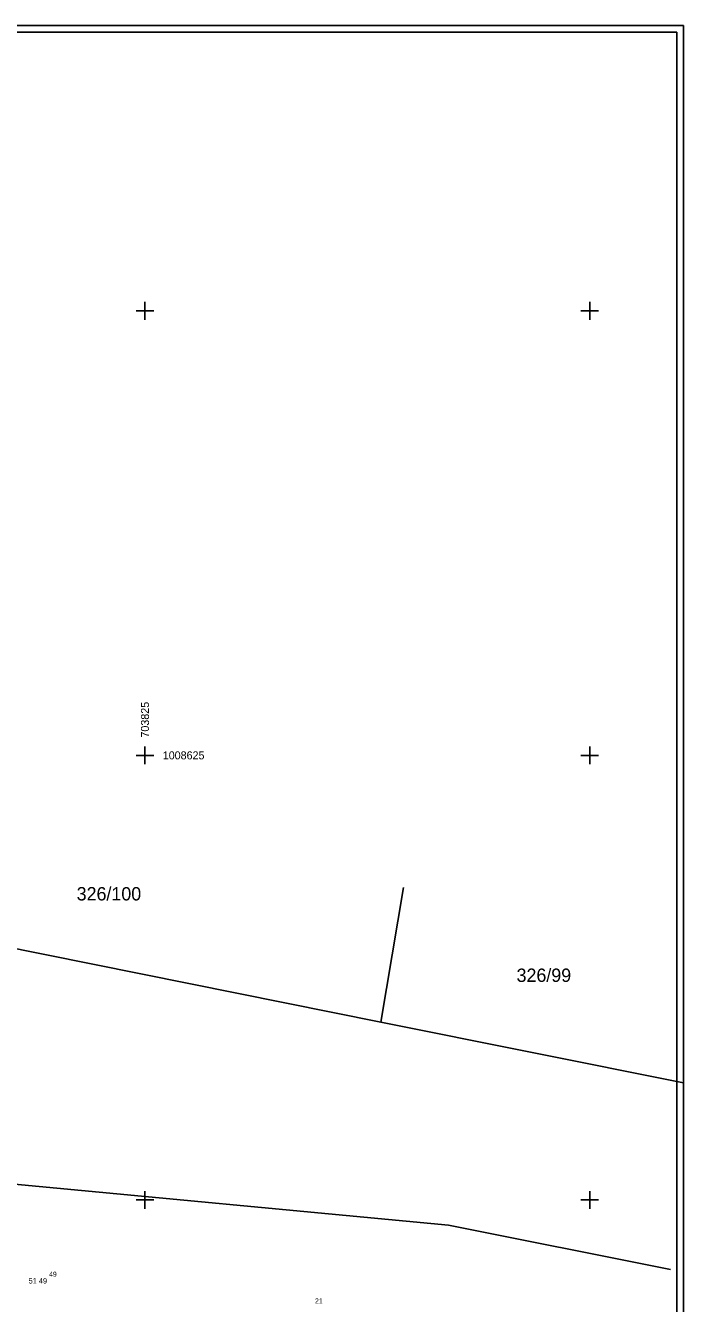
# Model space of a CAD drawing. Extents: x -704057 to -703795, y -1008732 to -1008584.
# Drawn here: x -703831.7 to -703794.7, y -1008655.8 to -1008584 of the extents above; entities that cross this region are included whole.
import ezdxf

# ---------------------------------------------------------------- set-up
doc = ezdxf.new("R2010")
doc.units = 0
for name, color, linetype in [('Z_body', 7, 'Continuous'), ('Z_body_cisla', 7, 'Continuous'), ('Z_body_vysky', 7, 'Continuous'), ('Z_hekt_sit', 7, 'Continuous'), ('Z_hekt_sit_popis', 7, 'Continuous'), ('Z_katastr_cisla_pozemkove', 7, 'Continuous'), ('Z_katastr_hranice', 7, 'Continuous'), ('Z_plotbox', 7, 'Continuous'), ('Z_ramecek_tisk', 7, 'Continuous')]:
    doc.layers.add(name, color=color, linetype=linetype)

# ---------------------------------------------------------------- blocks, each defined once
blk = doc.blocks.new('POINT_DISPLAY')
blk.add_line((0, 0), (0, 0))

msp = doc.modelspace()

# ---------------------------------------------------------------- linework, layer by layer
at = {"layer": 'Z_hekt_sit'}
for p, q in [((-703825, -1008599.5), (-703825, -1008600.5)), ((-703800, -1008599.5), (-703800, -1008600.5)), ((-703825.5, -1008600), (-703824.5, -1008600)), ((-703800.5, -1008600), (-703799.5, -1008600)), ((-703825, -1008624.5), (-703825, -1008625.5)), ((-703800, -1008624.5), (-703800, -1008625.5)), ((-703825.5, -1008625), (-703824.5, -1008625)), ((-703800.5, -1008625), (-703799.5, -1008625)), ((-703825, -1008649.5), (-703825, -1008650.5)), ((-703800, -1008649.5), (-703800, -1008650.5)), ((-703825.5, -1008650), (-703824.5, -1008650)), ((-703800.5, -1008650), (-703799.5, -1008650))]:
    msp.add_line(p, q, dxfattribs=at)
at = {"layer": 'Z_katastr_hranice'}
for p, q in [((-703811.75, -1008640), (-703810.47, -1008632.43)), ((-703843.15, -1008633.69), (-703811.75, -1008640)), ((-703811.75, -1008640), (-703794.73, -1008643.42)), ((-703807.93, -1008651.42), (-703891.93, -1008643.46)), ((-703795.45, -1008653.92), (-703807.93, -1008651.42))]:
    msp.add_line(p, q, dxfattribs=at)
at = {"layer": 'Z_plotbox'}
for p, q in [((-704057.23, -1008583.96), (-703794.73, -1008583.96)), ((-703794.73, -1008583.96), (-703794.73, -1008732.46))]:
    msp.add_line(p, q, dxfattribs=at)
at = {"layer": 'Z_ramecek_tisk'}
for p, q in [((-704056.86, -1008584.34), (-703795.11, -1008584.34)), ((-703795.11, -1008584.34), (-703795.11, -1008732.09))]:
    msp.add_line(p, q, dxfattribs=at)

# ---------------------------------------------------------------- block references
at = {"layer": 'Z_body'}
msp.add_blockref('POINT_DISPLAY', (-703830.89, -1008654.4), dxfattribs=at)

# ---------------------------------------------------------------- texts
at = {"layer": 'Z_body_cisla'}
for s, p in [('49', (-703830.39, -1008654.32)), ('21', (-703815.44, -1008655.82))]:
    msp.add_text(s, height=0.28, dxfattribs=at).set_placement(p)
at = {"layer": 'Z_body_vysky'}
msp.add_text('51 49', height=0.3, dxfattribs=at).set_placement((-703831.54, -1008654.7))
at = {"layer": 'Z_hekt_sit_popis'}
msp.add_text('703825', height=0.45, rotation=90, dxfattribs=at).set_placement((-703824.775, -1008624))
msp.add_text('1008625', height=0.45, dxfattribs=at).set_placement((-703824, -1008625.225))
at = {"layer": 'Z_katastr_cisla_pozemkove'}
for s, p in [('326/100', (-703828.84, -1008633.16)), ('326/99', (-703804.11, -1008637.74))]:
    msp.add_text(s, height=0.75, dxfattribs=at).set_placement(p)

doc.saveas('drawing.dxf')
